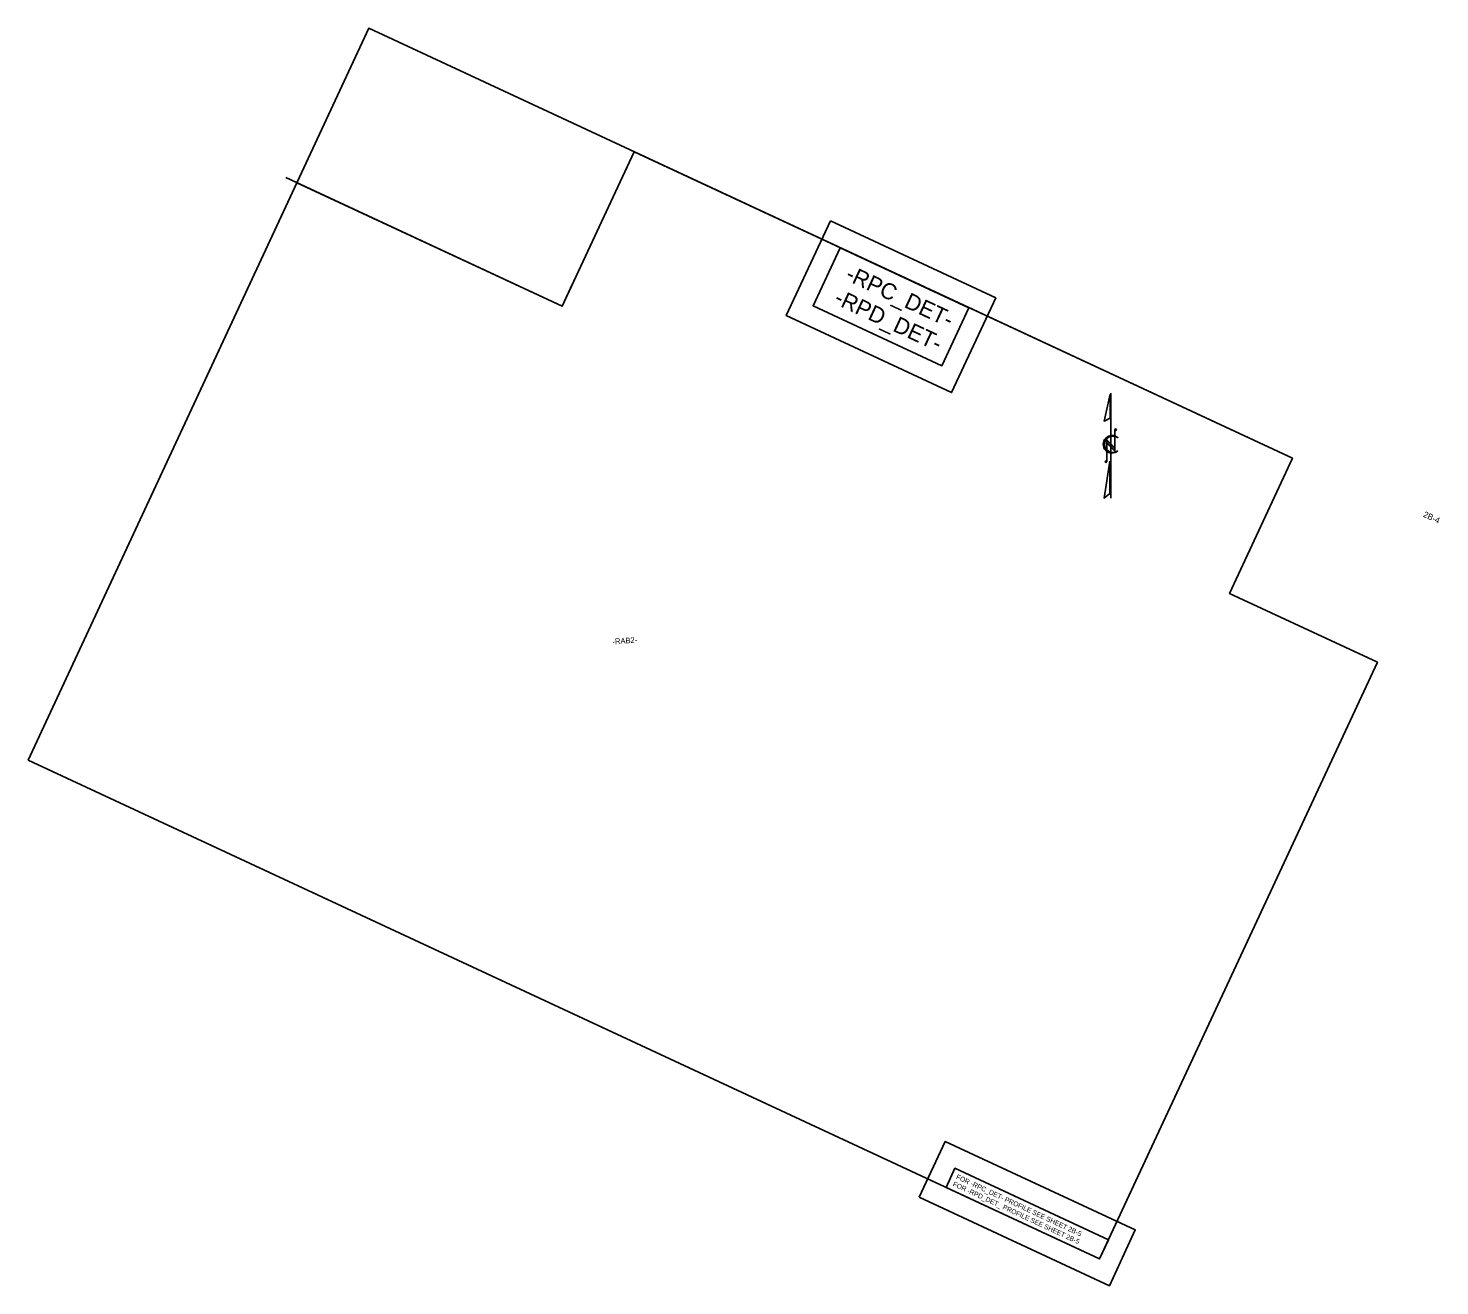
# Model space of a CAD drawing. Extents: x 2347572 to 2349321, y 843189 to 844747.
import ezdxf

# ---------------------------------------------------------------- set-up
doc = ezdxf.new("R2010")
doc.units = 0
for name, color, linetype in [('Prop Drainage Structure Headwall CELL', 7, 'Continuous'), ('Prop Drainage Structure Junction Box with Manhole CELL', 7, 'Continuous'), ('Prop Drainage Structure Pipe Collar CELL', 7, 'Continuous'), ('Prop Drainage Structure Pipe Stub Out CELL', 7, 'Continuous'), ('Prop Drainage Structure Plot Symbol 20 Scale', 7, 'Continuous'), ('Prop Drainage Structure Plot Symbol 20 Scale CELL', 7, 'Continuous'), ('Scratch_Level_3', 7, 'Continuous')]:
    doc.layers.add(name, color=color, linetype=linetype)

msp = doc.modelspace()

# ---------------------------------------------------------------- linework, layer by layer
at = {"layer": 'Prop Drainage Structure Headwall CELL'}
msp.add_lwpolyline([(2348709.4, 843311), (2348899.7, 843222.4), (2348910.8, 843246.2), (2348720.5, 843334.8)], close=True, dxfattribs=at)
at = {"layer": 'Prop Drainage Structure Pipe Collar CELL'}
msp.add_lwpolyline([(2348578.2, 844475.1), (2348737.8, 844400.8), (2348704.3, 844328.8), (2348544.7, 844403.2)], close=True, dxfattribs=at)
at = {"layer": 'Prop Drainage Structure Plot Symbol 20 Scale CELL'}
for p, q in [((2348913.7, 844164.9), (2348913.7, 844294.9)), ((2348918.6, 844249.7), (2348918.6, 844223)), ((2348918.6, 844227.2), (2348908.7, 844237.1)), ((2348908.7, 844237.1), (2348908.7, 844210)), ((2348918.6, 844226.2), (2348908.7, 844236.1)), ((2348908.7, 844236.1), (2348908.7, 844233.7)), ((2348918.6, 844223.8), (2348908.7, 844233.7)), ((2348908.7, 844233.7), (2348918.6, 844223.8)), ((2348918.6, 844223), (2348908.7, 844233)), ((2348918.6, 844223.8), (2348918.6, 844226.2)), ((2348922.3, 844239.8), (2348922.4, 844239.7))]:
    msp.add_line(p, q, dxfattribs=at)
for points in [[(2348912.8, 844293.8), (2348905.4, 844260), (2348912.8, 844263.8)], [(2348912.6, 844210.7), (2348905.3, 844164.9), (2348912.6, 844170.7)]]:
    msp.add_lwpolyline(points, close=True, dxfattribs=at)
for centre in [(2348919.7, 844249.7), (2348907.6, 844210)]:
    msp.add_circle(centre, 1.06, dxfattribs=at)
for centre, radius, start, end in [((2348915.1, 844231.6), 10.9, 47.84, 312.3941), ((2348916.1, 844231.6), 10.2, 53.095, 308.6287)]:
    msp.add_arc(centre, radius, start, end, dxfattribs=at)
at = {"layer": 'Scratch_Level_3'}
for p, q in [((2348233.9, 844402.6), (2347891.3, 844562.1)), ((2348246.8, 844430.5), (2348233.9, 844402.6))]:
    msp.add_line(p, q, dxfattribs=at)
for points in [[(2349243.9, 843961.6), (2349060.8, 844046.9), (2349138.7, 844214.2), (2347994.2, 844747), (2347572.2, 843840.4), (2348899.7, 843222.4)], [(2347572.2, 843840.4), (2347905.1, 844555.6), (2348233.9, 844402.6), (2348322.9, 844593.9), (2349138.7, 844214.2), (2349060.8, 844046.9), (2349243.9, 843961.6), (2348899.7, 843222.4)], [(2348566.1, 844508.3), (2348771, 844412.9), (2348716.4, 844295.6), (2348511.5, 844391)], [(2348676.2, 843298.9), (2348911.9, 843189.2), (2348944, 843258.3), (2348708.4, 843368)]]:
    msp.add_lwpolyline(points, close=True, dxfattribs=at)

# ---------------------------------------------------------------- texts
at = {"layer": 'Prop Drainage Structure Headwall CELL'}
for s, p in [('FOR -RPD_DET_ PROFILE SEE SHEET 2B-5', (2348717.2, 843313.1)), ('FOR -RPC_DET- PROFILE SEE SHEET 2B-5', (2348721.3, 843322))]:
    msp.add_text(s, height=6, rotation=335.0369, dxfattribs=at).set_placement(p)
at = {"layer": 'Prop Drainage Structure Junction Box with Manhole CELL'}
for s, p in [('-RPC_DET-', (2348583.5, 844435.8)), ('-RPD_DET-', (2348569.5, 844406.4))]:
    msp.add_text(s, height=20, rotation=335.0369, dxfattribs=at).set_placement(p)
at = {"layer": 'Prop Drainage Structure Pipe Stub Out CELL'}
msp.add_text('2B-4', height=7.5, rotation=335.0369, dxfattribs=at).set_placement((2349300, 844142.1))
at = {"layer": 'Prop Drainage Structure Plot Symbol 20 Scale'}
msp.add_text('-RAB2-', height=7, rotation=4.4374, dxfattribs=at).set_placement((2348296.4, 843983.6))

doc.saveas('drawing.dxf')
